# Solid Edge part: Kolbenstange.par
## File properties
Username: bmolnar
Dokumentum tartalom típus: 0
Author: bmolnar
Last saved by: bmolnar
Revision: 88
Sűrűség: 0,000 kg/m^3
Pontosság: 0,990
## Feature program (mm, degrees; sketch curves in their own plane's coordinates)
base feature "unnamed BaseFeature 1"
sketch for "unnamed Protrusion 1" plane through (34.5, 0, 0) normal (1, 0, 0) x-axis (0, 0, -1)
  circle centre (0, 0) radius 50
extrude "unnamed Protrusion 1" add finite 14 along +normal
sketch for "Furat_1" plane through (-75, 0, 0) normal (-1, 0, 0) x-axis (0, 0, 1)
  hole centre (0, 0) bore radius 5.053
hole "Furat_1" nominal diameter 12 finite  ThreadDepth = 22 mm
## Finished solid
Body 1: solid body, 14 faces, 20 edges, 8 vertices.
  Faces by surface: plane 8, cylinder 4, cone 1, torus 1
  Edges by curve: circle 10, line 6, ellipse 2, intersection 2
Bounding box of the edges (mm; curved faces can reach further): 123.545 x 100.000 x 100.000, from (-75.0451, -50, -50) to (48.5, 50, 50).
Cylindrical faces by radius (mm): R5.053 x2, R12.5 x1, R50 x1
Conical faces (half-angle, radius in mm at the cone's reference point): 45 deg R5.553 x1
Toroidal faces (ring radius, tube radius in mm): R10.7 r1.8 x1
Planar faces by outward normal: +x 1, +y 1, -x 3, -y 1, oblique 2
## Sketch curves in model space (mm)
circle centre (34.5, 0, 0) radius 50
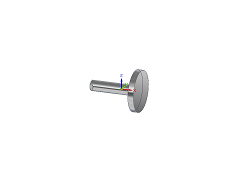
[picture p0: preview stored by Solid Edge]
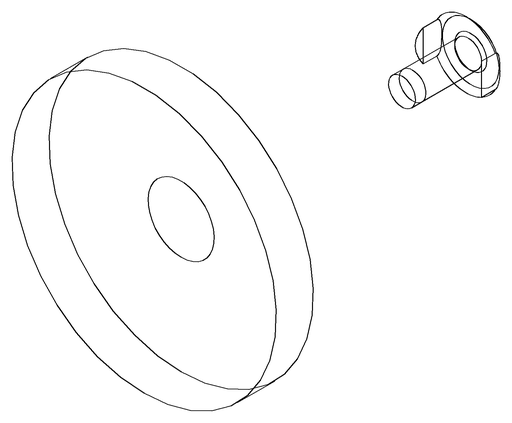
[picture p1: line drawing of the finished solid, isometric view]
